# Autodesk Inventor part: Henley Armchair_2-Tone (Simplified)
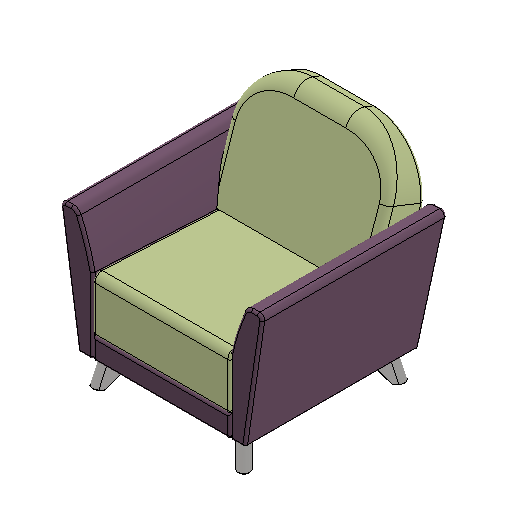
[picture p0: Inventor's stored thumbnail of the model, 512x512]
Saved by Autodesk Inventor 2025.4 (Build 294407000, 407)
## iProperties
Created: 2026-05
Part Number: Henley Armchair_2-Tone (Simplified)
Material: Generic
Description: ARMCHAIR
Document SubType Name: Modeling
Designer: Brian.Thangei
Density: 1 g/cm^3
Appearance: Default
Project: HENLEY
Sending System: SolidWorks 2026
Preprocessor: SwSTEP 2.0
Title: Henley Armchiar.STEP
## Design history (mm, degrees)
feature "NONE"
feature "NONE:1"
feature "NONE:2"
feature "NONE:3"
feature "NONE:4"
feature "NONE:5"
feature "NONE:6"
feature "NONE:7"
feature "NONE:8"
workplane "Work Plane1"
workplane "Work Plane2"
workplane "Work Plane3"
workplane "Work Plane4"
workplane "Work Plane5"
node "Direct Edit1"
node "SEAT"
node "BASE"
node "ARM"
node "FOOT"
node "ARM2"
node "FOOT2"
node "FOOT3"
node "FOOT4"
node "BACK"
move_body "Move1" dims "d0" = 10
move_body "Move2" dims "d3" = -10
other parameters: "d1" = 0, "d2" = 0, "d4" = 0, "d5" = 0
